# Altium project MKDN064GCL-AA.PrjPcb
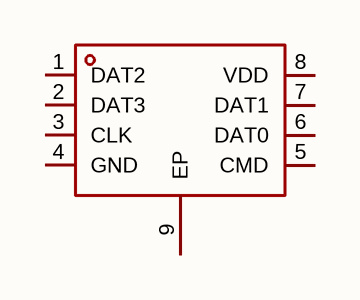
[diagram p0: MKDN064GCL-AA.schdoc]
1 sheet, 1 parts. Net scope: global (net labels, ports and power ports of the same name join across sheets).

## Sheet MKDN064GCL-AA.schdoc
size 127 x 101 mm

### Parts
U?  mkdn064gcl-aa  [LGA-16_L12.5-W9.0-P1.27-TL-EP]  (value not drawn)

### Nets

Not connected (* = marked no-connect by the designer): U? 1(DAT2) 2(DAT3) 3(CLK) 4(GND) 5(CMD) 6(DAT0) 7(DAT1) 8(VDD) 9(EP)

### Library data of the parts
U? = mkdn064gcl-aa: 存储容量:64Gbit;时钟频率(fc):208MHz;工作电压:2.7V~3.6V;; Manufacturer: MK(米客方德); AddInBom: yes; ModelId: aae4acadbbb4480ebd429fe2f08c27d7; ModelTransform: 492.125,354.33,0,0,0,0,0,0,0; Memory Size: 64Gbit; Interface: SD接口；SPI; Clock Frequency: 208MHz; Standby Supply Current: 250uA; Program / Erase Cycles: 5千次; ECC: 有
